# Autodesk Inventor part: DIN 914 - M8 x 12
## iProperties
Created: 2006-02
Part Number: DIN 914 - M8 x 12
Material: Steel, Mild
Description: Hexagon Socket Set Screw
Document SubType Name: Modeling
Standard: DIN 914
Designer: Andy Moles
Standards Organization: DIN
Language: en-US
Size Designation: M8 x 12
Categories: <MemberInstance><Categories><Category DisplayName="Fasteners" InternalName="e4da775c-781d-43d5-af7c-5136215cf5a6" Mnemonic="FSTN"><Category DisplayName="Bolts"
Density: 7.86 g/cm^3
Author: Andy Moles
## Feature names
1. Body [Revolution]
2. Slot [Extrusion]
3. Chamfer1
4. Chamfer2
